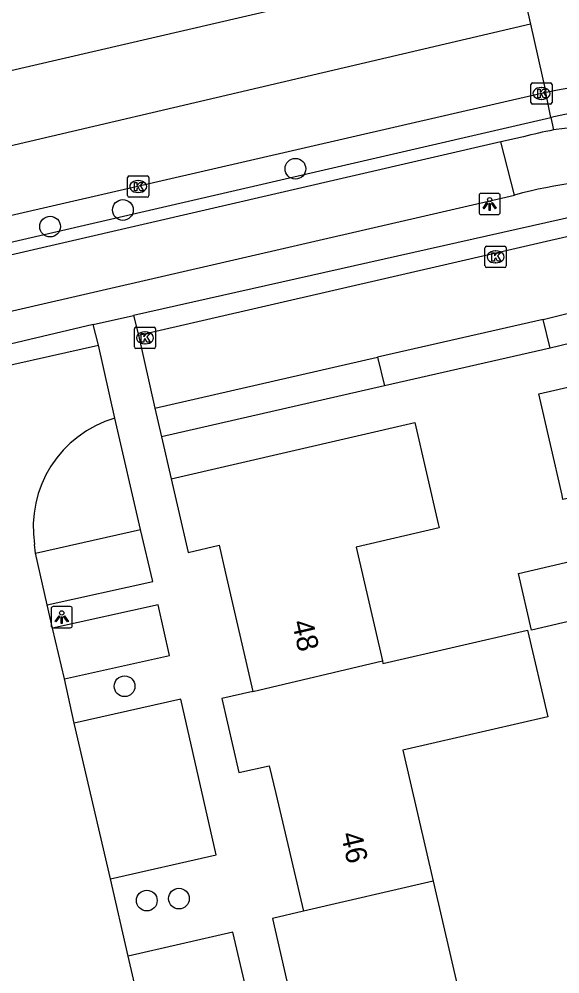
# Model space of a CAD drawing. Extents: x 156414 to 157775, y 382335 to 383765.
# Drawn here: x 156916.44 to 156941.94, y 382923.76 to 382968.78 of the extents above; entities that cross this region are included whole.
import ezdxf

# ---------------------------------------------------------------- set-up
doc = ezdxf.new("R2010")
doc.units = 0
for name, color, linetype in [('IMGEO_Berm_groen', 7, 'Continuous'), ('IMGEO_Boom', 7, 'Continuous'), ('IMGEO_Fietspad_gesloten', 7, 'Continuous'), ('IMGEO_Haag', 7, 'Continuous'), ('IMGEO_Kolk', 7, 'Continuous'), ('IMGEO_Lichtpunt', 7, 'Continuous'), ('IMGEO_Pand', 7, 'Continuous'), ('IMGEO_Pand_nummerreeks', 7, 'Continuous'), ('IMGEO_Parkeervlak_open', 7, 'Continuous'), ('IMGEO_Rijbaan_lokaal_gesloten', 7, 'Continuous'), ('IMGEO_Rijbaan_lokaal_open', 7, 'Continuous'), ('IMGEO_Rijbaan_regionaal_gesloten', 7, 'Continuous'), ('IMGEO_Verkeerseiland_open', 7, 'Continuous'), ('IMGEO_Voetpad_open', 7, 'Continuous')]:
    doc.layers.add(name, color=color, linetype=linetype)

msp = doc.modelspace()

# ---------------------------------------------------------------- linework, layer by layer
at = {"layer": 'IMGEO_Berm_groen'}
for points in [[(156943.885, 382953.85), (156941.48, 382953.262)], [(156933.668, 382951.485), (156923.153, 382949.089)]]:
    msp.add_lwpolyline(points, dxfattribs=at)
at = {"layer": 'IMGEO_Boom'}
for centre in [(156929.468, 382961.722), (156921.335, 382959.778), (156917.903, 382958.994), (156921.415, 382937.322), (156923.977, 382927.31), (156922.462, 382927.218)]:
    msp.add_circle(centre, 0.489, dxfattribs=at)
at = {"layer": 'IMGEO_Fietspad_gesloten'}
for points in [[(156939.156, 382962.984), (156887.943, 382951.159)], [(156940.214, 382963.228), (156939.156, 382962.984)], [(156939.803, 382960.484), (156939.156, 382962.984)], [(156913.318, 382954.385), (156939.803, 382960.484)]]:
    msp.add_lwpolyline(points, dxfattribs=at)
for centre, radius, start, end in [((156945.236, 382940.355), 23.474, 57.5864, 98.8301), ((156945.915, 382941.46), 22.502, 100.9704, 104.6766), ((156945.631, 382938.914), 22.343, 74.1693, 105.1195)]:
    msp.add_arc(centre, radius, start, end, dxfattribs=at)
at = {"layer": 'IMGEO_Haag'}
for points in [[(156887.799, 382951.74), (156941.504, 382964.137)], [(156941.504, 382964.137), (156941.633, 382963.551)]]:
    msp.add_lwpolyline(points, dxfattribs=at)
at = {"layer": 'IMGEO_Kolk'}
for p, q in [((156940.568, 382964.845), (156940.568, 382965.697)), ((156940.643, 382965.771), (156941.495, 382965.771)), ((156941.569, 382965.697), (156941.569, 382964.845)), ((156941.056, 382965.551), (156941.081, 382965.551)), ((156941.495, 382964.771), (156940.643, 382964.771)), ((156941.079, 382964.991), (156941.054, 382964.991)), ((156921.555, 382960.455), (156921.555, 382961.307)), ((156921.63, 382961.381), (156922.482, 382961.381)), ((156922.043, 382961.161), (156922.068, 382961.161)), ((156922.556, 382961.307), (156922.556, 382960.455)), ((156922.482, 382960.381), (156921.63, 382960.381)), ((156922.066, 382960.601), (156922.041, 382960.601)), ((156938.405, 382957.139), (156938.405, 382957.991)), ((156938.48, 382958.065), (156939.332, 382958.065)), ((156939.406, 382957.991), (156939.406, 382957.139)), ((156938.893, 382957.845), (156938.918, 382957.845)), ((156939.332, 382957.065), (156938.48, 382957.065)), ((156938.916, 382957.285), (156938.891, 382957.285)), ((156921.876, 382953.322), (156921.876, 382954.174)), ((156921.951, 382954.248), (156922.803, 382954.248)), ((156922.364, 382954.028), (156922.389, 382954.028)), ((156922.877, 382954.174), (156922.877, 382953.322)), ((156922.387, 382953.468), (156922.362, 382953.468)), ((156922.803, 382953.248), (156921.951, 382953.248))]:
    msp.add_line(p, q, dxfattribs=at)
for points in [[(156940.568, 382964.845), (156940.568, 382965.697)], [(156940.643, 382965.771), (156941.495, 382965.771)], [(156941.569, 382965.697), (156941.569, 382964.845)], [(156940.889, 382965.471), (156941.012, 382965.471), (156941.012, 382965.32), (156941.142, 382965.471), (156941.306, 382965.471), (156941.16, 382965.32), (156941.313, 382965.071), (156941.161, 382965.071), (156941.076, 382965.235), (156941.012, 382965.168), (156941.012, 382965.071), (156940.889, 382965.071), (156940.889, 382965.471)], [(156941.495, 382964.771), (156940.643, 382964.771)], [(156921.555, 382960.455), (156921.555, 382961.307)], [(156921.63, 382961.381), (156922.482, 382961.381)], [(156922.556, 382961.307), (156922.556, 382960.455)], [(156921.876, 382961.081), (156921.999, 382961.081), (156921.999, 382960.93), (156922.129, 382961.081), (156922.293, 382961.081), (156922.147, 382960.93), (156922.3, 382960.681), (156922.148, 382960.681), (156922.063, 382960.845), (156921.999, 382960.778), (156921.999, 382960.681), (156921.876, 382960.681), (156921.876, 382961.081)], [(156922.482, 382960.381), (156921.63, 382960.381)], [(156938.405, 382957.139), (156938.405, 382957.991)], [(156938.48, 382958.065), (156939.332, 382958.065)], [(156939.406, 382957.991), (156939.406, 382957.139)], [(156938.726, 382957.765), (156938.849, 382957.765), (156938.849, 382957.614), (156938.979, 382957.765), (156939.143, 382957.765), (156938.997, 382957.614), (156939.15, 382957.365), (156938.998, 382957.365), (156938.913, 382957.529), (156938.849, 382957.462), (156938.849, 382957.365), (156938.726, 382957.365), (156938.726, 382957.765)], [(156939.332, 382957.065), (156938.48, 382957.065)], [(156921.876, 382953.322), (156921.876, 382954.174)], [(156921.951, 382954.248), (156922.803, 382954.248)], [(156922.197, 382953.948), (156922.32, 382953.948), (156922.32, 382953.797), (156922.45, 382953.948), (156922.614, 382953.948), (156922.468, 382953.797), (156922.621, 382953.548), (156922.469, 382953.548), (156922.384, 382953.712), (156922.32, 382953.645), (156922.32, 382953.548), (156922.197, 382953.548), (156922.197, 382953.948)], [(156922.877, 382954.174), (156922.877, 382953.322)], [(156922.803, 382953.248), (156921.951, 382953.248)]]:
    msp.add_lwpolyline(points, dxfattribs=at)
for centre, start, end in [((156940.645, 382965.695), 91.552, 178.448), ((156940.645, 382965.695), 91.552, 178.448), ((156941.493, 382965.695), 1.552, 88.448), ((156941.493, 382965.695), 1.552, 88.448), ((156940.645, 382964.847), 181.552, 268.448), ((156940.645, 382964.847), 181.552, 268.448), ((156941.493, 382964.847), 271.552, 358.448), ((156941.493, 382964.847), 271.552, 358.448), ((156921.632, 382961.305), 91.552, 178.448), ((156921.632, 382961.305), 91.552, 178.448), ((156922.48, 382961.305), 1.552, 88.448), ((156922.48, 382961.305), 1.552, 88.448), ((156921.632, 382960.457), 181.552, 268.448), ((156921.632, 382960.457), 181.552, 268.448), ((156922.48, 382960.457), 271.552, 358.448), ((156922.48, 382960.457), 271.552, 358.448), ((156938.482, 382957.989), 91.552, 178.448), ((156938.482, 382957.989), 91.552, 178.448), ((156939.33, 382957.989), 1.552, 88.448), ((156939.33, 382957.989), 1.552, 88.448), ((156938.482, 382957.141), 181.552, 268.448), ((156938.482, 382957.141), 181.552, 268.448), ((156939.33, 382957.141), 271.552, 358.448), ((156939.33, 382957.141), 271.552, 358.448), ((156921.953, 382954.172), 91.552, 178.448), ((156921.953, 382954.172), 91.552, 178.448), ((156922.801, 382954.172), 1.552, 88.448), ((156922.801, 382954.172), 1.552, 88.448), ((156921.953, 382953.324), 181.552, 268.448), ((156921.953, 382953.324), 181.552, 268.448), ((156922.801, 382953.324), 271.552, 358.448), ((156922.801, 382953.324), 271.552, 358.448)]:
    msp.add_arc(centre, 0.0765, start, end, dxfattribs=at)
for centre, major_axis, ratio, start_param, end_param in [((156941.055, 382965.271), (-0.387, 0.002), 0.722429, 4.712389, 7.853982), ((156941.08, 382965.271), (-0.39, 0.002), 0.717154, 1.570796, 4.712389), ((156922.042, 382960.881), (-0.387, 0.002), 0.722429, 4.712389, 7.853982), ((156922.067, 382960.881), (-0.39, 0.002), 0.717154, 1.570796, 4.712389), ((156938.892, 382957.565), (-0.387, 0.002), 0.722429, 4.712389, 7.853982), ((156938.917, 382957.565), (-0.39, 0.002), 0.717154, 1.570796, 4.712389), ((156922.363, 382953.748), (-0.387, 0.002), 0.722429, 4.712389, 7.853982), ((156922.388, 382953.748), (-0.39, 0.002), 0.717154, 1.570796, 4.712389)]:
    msp.add_ellipse(centre, major_axis=major_axis, ratio=ratio, start_param=start_param, end_param=end_param, dxfattribs=at)
at = {"layer": 'IMGEO_Lichtpunt'}
for p, q in [((156938.125, 382960.464), (156938.125, 382959.657)), ((156938.125, 382960.464), (156938.125, 382959.657)), ((156939.027, 382960.559), (156938.219, 382960.559)), ((156939.027, 382960.559), (156938.219, 382960.559)), ((156939.121, 382959.657), (156939.121, 382960.464)), ((156939.121, 382959.657), (156939.121, 382960.464)), ((156938.219, 382959.563), (156939.027, 382959.563)), ((156938.219, 382959.563), (156939.027, 382959.563)), ((156917.953, 382940.982), (156917.953, 382940.175)), ((156917.953, 382940.982), (156917.953, 382940.175)), ((156918.855, 382941.077), (156918.047, 382941.077)), ((156918.855, 382941.077), (156918.047, 382941.077)), ((156918.949, 382940.175), (156918.949, 382940.982)), ((156918.949, 382940.175), (156918.949, 382940.982)), ((156918.047, 382940.081), (156918.855, 382940.081)), ((156918.047, 382940.081), (156918.855, 382940.081))]:
    msp.add_line(p, q, dxfattribs=at)
for points in [[(156938.499, 382960.128), (156938.538, 382960.1), (156938.35, 382959.838), (156938.312, 382959.865), (156938.499, 382960.128)], [(156938.601, 382960.08), (156938.648, 382960.08), (156938.648, 382959.758), (156938.601, 382959.758), (156938.601, 382960.08)], [(156938.711, 382960.1), (156938.749, 382960.127), (156938.936, 382959.865), (156938.897, 382959.837), (156938.711, 382960.1)], [(156918.327, 382940.646), (156918.366, 382940.618), (156918.178, 382940.356), (156918.14, 382940.383), (156918.327, 382940.646)], [(156918.429, 382940.598), (156918.476, 382940.598), (156918.476, 382940.276), (156918.429, 382940.276), (156918.429, 382940.598)], [(156918.539, 382940.618), (156918.577, 382940.645), (156918.764, 382940.383), (156918.725, 382940.355), (156918.539, 382940.618)]]:
    msp.add_lwpolyline(points, dxfattribs=at)
for centre in [(156938.624, 382960.262), (156918.452, 382940.78)]:
    msp.add_circle(centre, 0.0994, dxfattribs=at)
for centre, start, end in [((156938.219, 382960.464), 90, 180), ((156938.219, 382960.464), 90, 180), ((156939.027, 382960.464), 0, 90), ((156939.027, 382960.464), 0, 90), ((156938.219, 382959.657), 180, 270), ((156938.219, 382959.657), 180, 270), ((156939.027, 382959.657), 270, 0), ((156939.027, 382959.657), 270, 360), ((156918.047, 382940.982), 90, 180), ((156918.047, 382940.982), 90, 180), ((156918.855, 382940.982), 0, 90), ((156918.855, 382940.982), 0, 90), ((156918.047, 382940.175), 180, 270), ((156918.047, 382940.175), 180, 270), ((156918.855, 382940.175), 270, 0), ((156918.855, 382940.175), 270, 360)]:
    msp.add_arc(centre, 0.0946, start, end, dxfattribs=at)
at = {"layer": 'IMGEO_Pand'}
for points in [[(156947.27, 382941.312), (156947.231, 382941.479), (156946.995, 382942.502), (156945.95, 382947.023), (156942.082, 382946.132), (156942.037, 382946.327), (156940.936, 382951.102), (156948.004, 382952.731), (156948.396, 382951.045), (156951.381, 382951.731), (156952.389, 382947.377), (156955.398, 382948.066), (156956.474, 382943.428), (156954.652, 382943.009), (156950.939, 382942.155)], [(156923.606, 382947.103), (156935.097, 382949.756), (156936.197, 382944.981), (156936.242, 382944.786), (156932.327, 382943.884), (156933.568, 382938.516)], [(156923.606, 382947.103), (156924.417, 382943.627), (156925.869, 382943.974), (156926.174, 382942.659), (156927.468, 382937.075)], [(156939.981, 382942.644), (156943.671, 382943.497), (156944.288, 382940.825), (156940.598, 382939.972), (156939.981, 382942.644)], [(156933.568, 382938.516), (156933.595, 382938.399), (156940.416, 382939.971), (156941.36, 382935.888), (156934.538, 382934.316), (156935.969, 382928.126)], [(156927.468, 382937.075), (156933.568, 382938.516)], [(156927.468, 382937.075), (156926.003, 382936.749), (156926.795, 382933.256), (156928.237, 382933.576), (156928.545, 382932.269), (156929.849, 382926.712)], [(156935.969, 382928.126), (156929.849, 382926.712)], [(156935.969, 382928.126), (156938.368, 382917.746)], [(156929.849, 382926.712), (156928.384, 382926.373), (156929.194, 382922.874), (156930.652, 382923.212), (156930.955, 382921.896), (156932.236, 382916.329)]]:
    msp.add_lwpolyline(points, dxfattribs=at)
at = {"layer": 'IMGEO_Parkeervlak_open'}
msp.add_lwpolyline([(156917.215, 382943.593), (156922.169, 382944.706)], dxfattribs=at)
at = {"layer": 'IMGEO_Rijbaan_lokaal_gesloten'}
for points in [[(156913.862, 382951.989), (156920.182, 382953.408)], [(156920.956, 382949.965), (156920.182, 382953.408)], [(156917.215, 382943.593), (156917.168, 382944.011)], [(156917.767, 382941.168), (156917.215, 382943.593)], [(156918.011, 382940.069), (156917.767, 382941.168)], [(156918.574, 382937.671), (156918.011, 382940.069)], [(156919.045, 382935.586), (156918.574, 382937.671)], [(156920.758, 382928.243), (156919.045, 382935.586)], [(156921.59, 382924.592), (156920.758, 382928.243)], [(156923.616, 382915.861), (156921.59, 382924.592)]]:
    msp.add_lwpolyline(points, dxfattribs=at)
msp.add_arc((156922.458, 382944.828), 5.352, 106.2939, 188.7762, dxfattribs=at)
at = {"layer": 'IMGEO_Rijbaan_lokaal_open'}
for points in [[(156922.072, 382953.868), (156943.287, 382958.756)], [(156941.148, 382954.622), (156943.531, 382955.205)], [(156941.148, 382954.622), (156933.342, 382952.843)], [(156941.48, 382953.262), (156941.148, 382954.622)], [(156922.072, 382953.868), (156922.846, 382950.439)], [(156941.48, 382953.262), (156933.668, 382951.485)], [(156922.846, 382950.439), (156933.342, 382952.843)], [(156933.342, 382952.843), (156933.668, 382951.485)]]:
    msp.add_lwpolyline(points, dxfattribs=at)
at = {"layer": 'IMGEO_Rijbaan_regionaal_gesloten'}
for points in [[(156939.797, 382971.848), (156903.004, 382963.32), (156830.232, 382946.499), (156816.29, 382943.135), (156816.196, 382943.116)], [(156939.797, 382971.848), (156940.547, 382968.546)], [(156940.547, 382968.546), (156903.126, 382959.769), (156893.4, 382957.443)], [(156940.547, 382968.546), (156941.281, 382965.316)], [(156941.281, 382965.316), (156941.062, 382965.269), (156911.64, 382958.497)]]:
    msp.add_lwpolyline(points, dxfattribs=at)
msp.add_arc((156946.534, 382940.48), 25.385, 62.6759, 101.9417, dxfattribs=at)
at = {"layer": 'IMGEO_Verkeerseiland_open'}
msp.add_lwpolyline([(156941.504, 382964.137), (156941.281, 382965.316)], dxfattribs=at)
msp.add_arc((156946.547, 382941.181), 23.504, 50.4056, 102.3894, dxfattribs=at)
at = {"layer": 'IMGEO_Voetpad_open'}
for points in [[(156942.674, 382959.488), (156921.828, 382954.805)], [(156919.93, 382954.371), (156921.828, 382954.805)], [(156921.828, 382954.805), (156922.072, 382953.868)], [(156919.93, 382954.371), (156913.617, 382952.879)], [(156920.182, 382953.408), (156919.93, 382954.371)], [(156922.846, 382950.439), (156923.153, 382949.089)], [(156922.169, 382944.706), (156920.956, 382949.965)], [(156923.153, 382949.089), (156923.606, 382947.103)], [(156917.767, 382941.168), (156922.743, 382942.255), (156922.169, 382944.706)], [(156918.574, 382937.671), (156923.534, 382938.772), (156922.992, 382941.169), (156918.011, 382940.069)], [(156920.758, 382928.243), (156925.732, 382929.367), (156924.059, 382936.717), (156919.045, 382935.586)], [(156928.578, 382916.965), (156926.514, 382925.73), (156921.59, 382924.592)]]:
    msp.add_lwpolyline(points, dxfattribs=at)

# ---------------------------------------------------------------- texts
at = {"layer": 'IMGEO_Pand_nummerreeks'}
for s, p in [('48', (156929.294, 382940.341)), ('46', (156931.6, 382930.347))]:
    msp.add_text(s, height=1, rotation=282.9936, dxfattribs=at).set_placement(p)

doc.saveas('drawing.dxf')
